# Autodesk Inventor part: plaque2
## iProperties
Created: 2009-01
Part Number: plaque2
Document SubType Name: Modeling
Designer: LECHENAULT
Author: LECHENAULT
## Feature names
1. Extrusion1
2. Extrusion2
3. Extrusion3
4. Extrusion4
